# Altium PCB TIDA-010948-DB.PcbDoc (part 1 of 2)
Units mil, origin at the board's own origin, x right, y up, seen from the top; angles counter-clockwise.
Board outline 8000 x 3300 mil, 4 copper layers (Top Layer, Mid-Layer 1, Mid-Layer 2, Bottom Layer), stack 61.2 mil thick; 16 components, 34 nets, 141 pads, 139 vias.
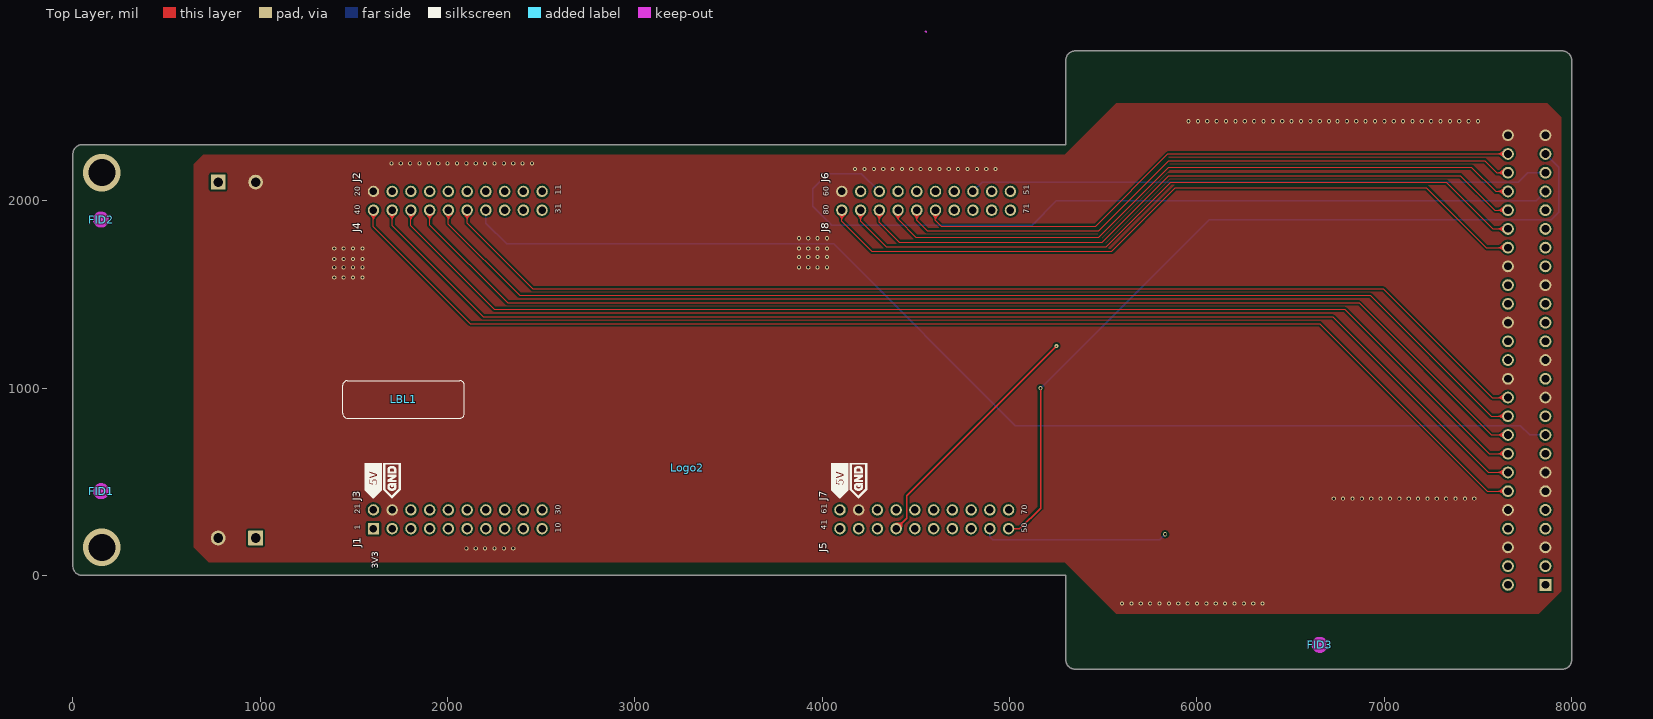
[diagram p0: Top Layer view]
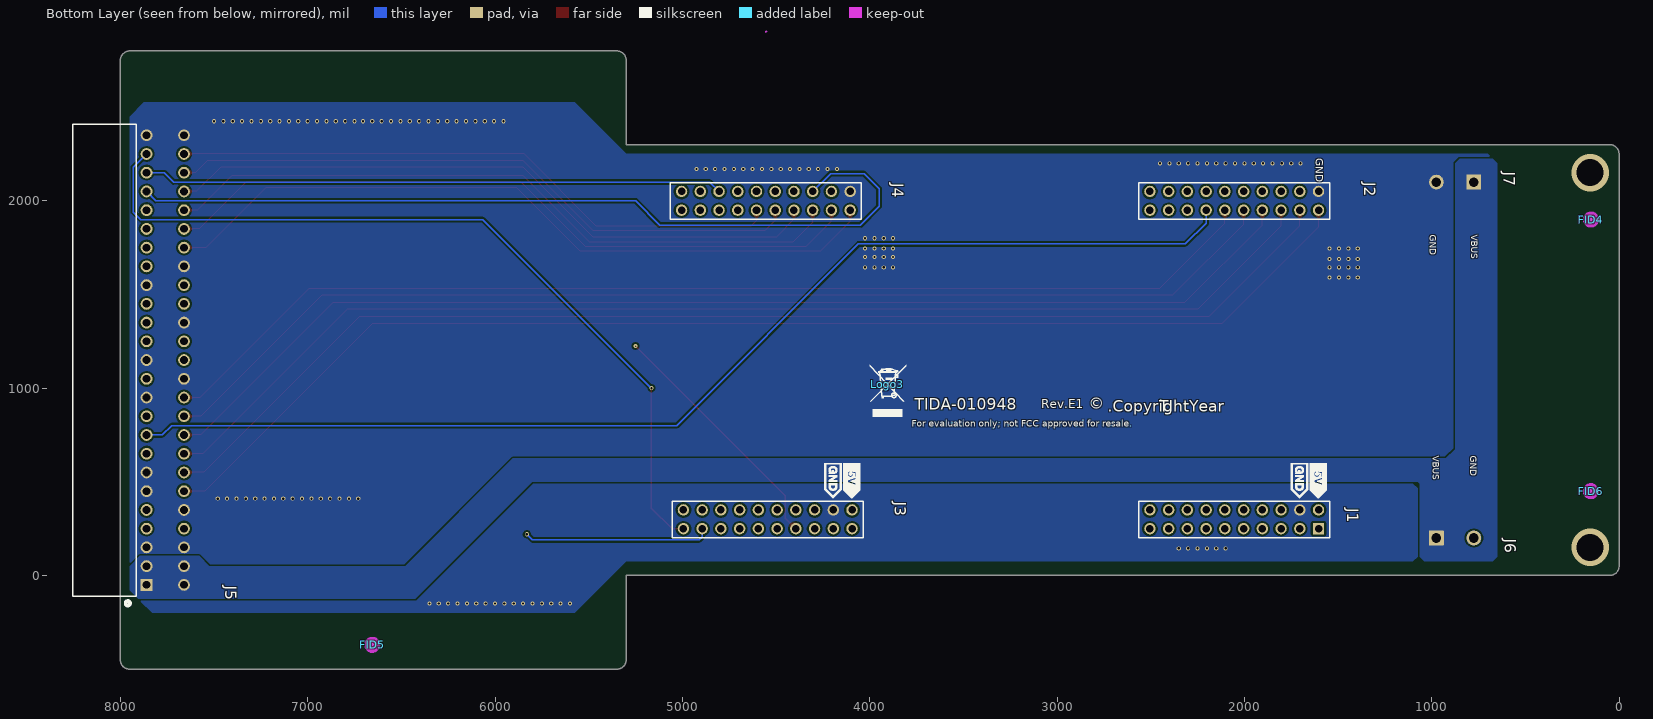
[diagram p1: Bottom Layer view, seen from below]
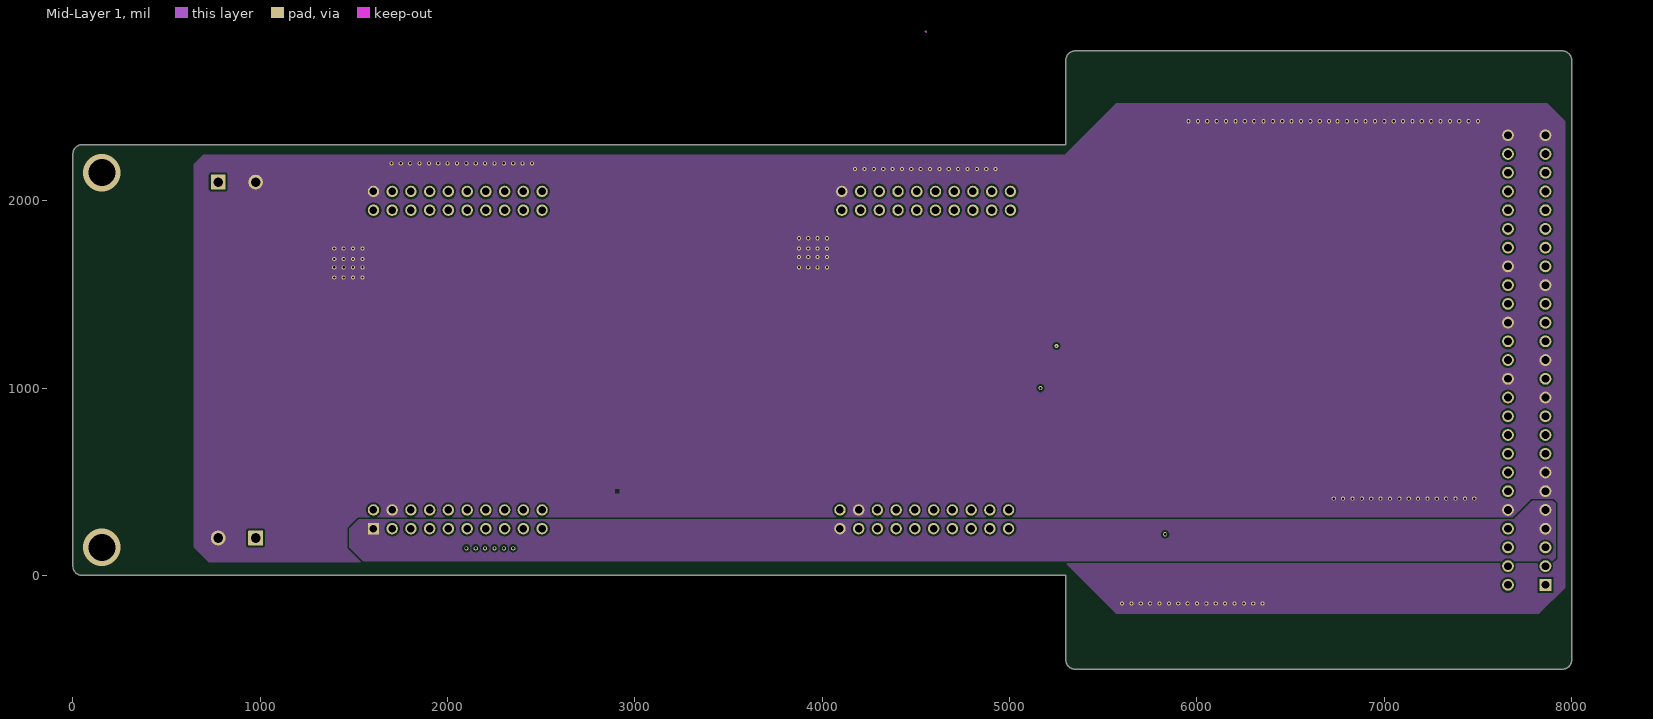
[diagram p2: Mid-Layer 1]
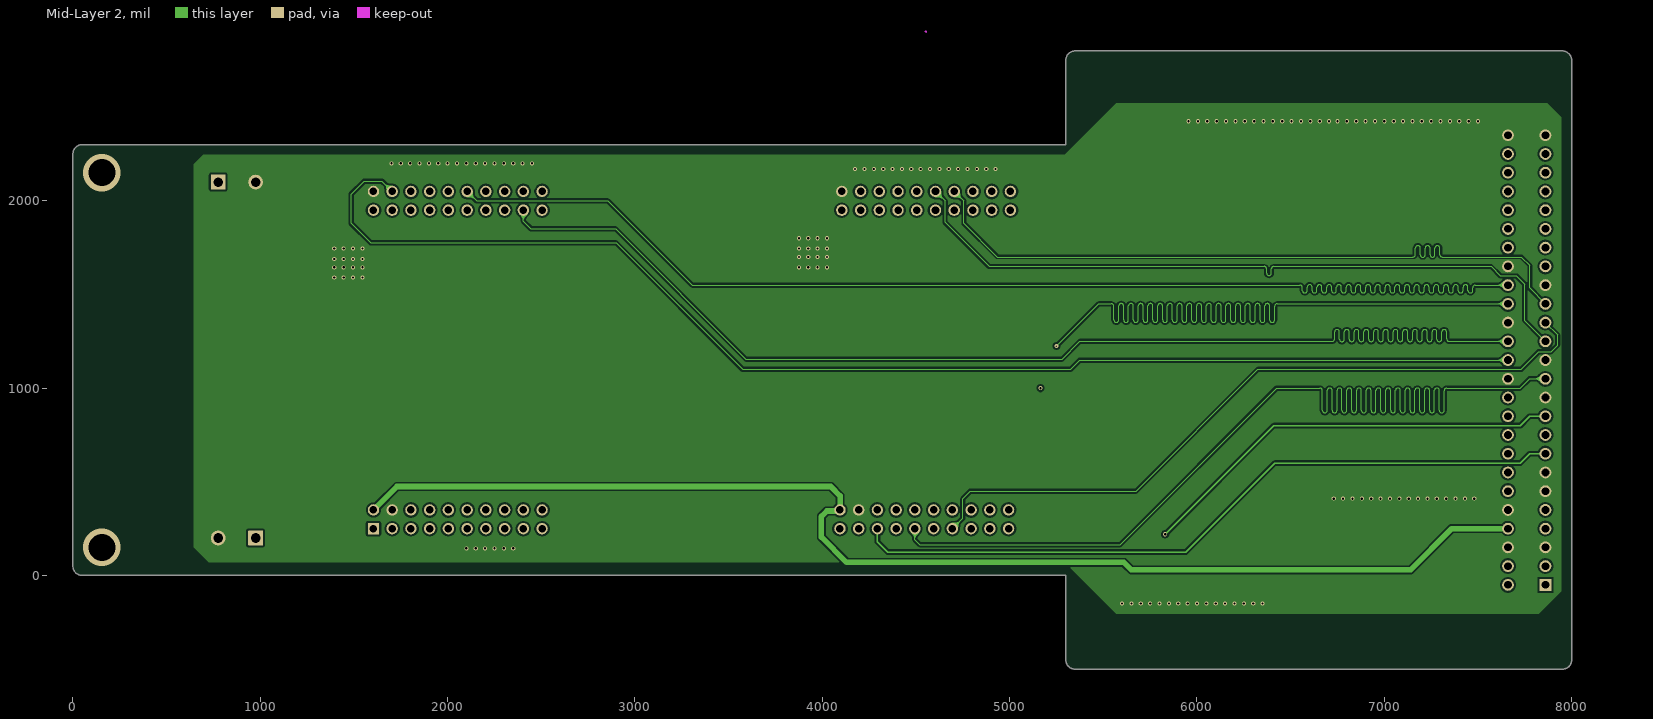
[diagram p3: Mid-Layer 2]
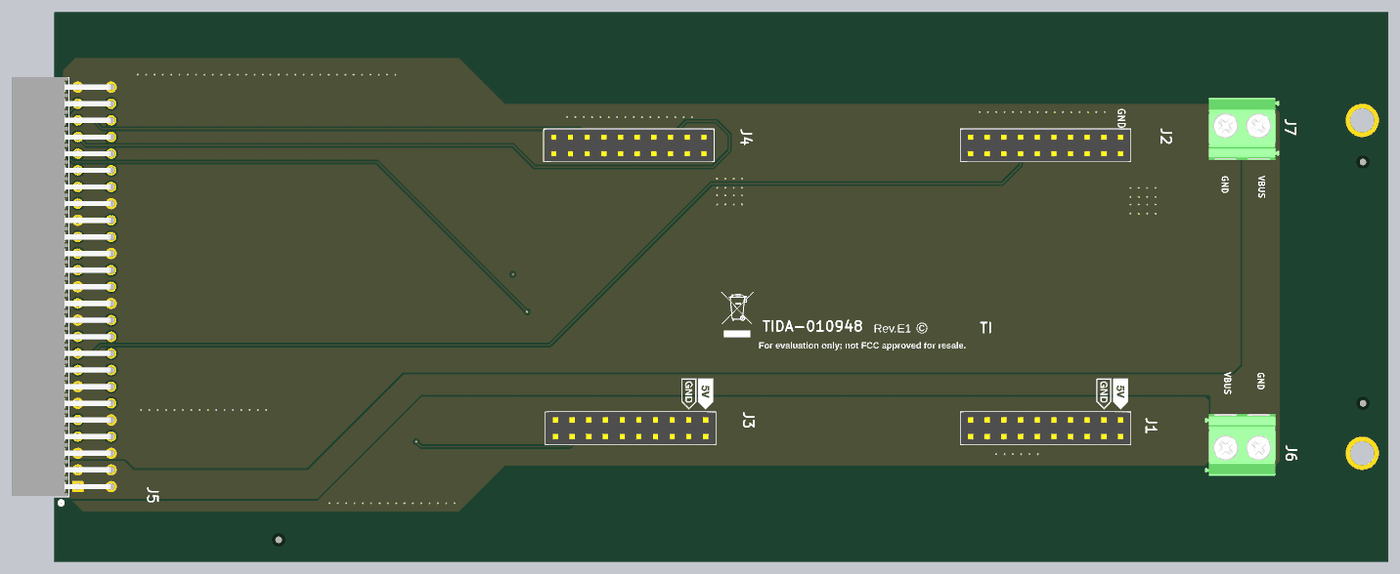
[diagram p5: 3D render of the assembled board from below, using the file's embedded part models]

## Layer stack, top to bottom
Top Solder: solder mask 0.4, Solder Resist, Dk 3.5
Top Layer: signal copper 1.4
Dielectric1: core 10, FR-4, Dk 4.2
Mid-Layer 1: signal copper 1.417
Dielectric2: prepreg 35.566, FR-4, Dk 4.2
Mid-Layer 2: signal copper 1.417
Dielectric 3: core 10, FR-4, Dk 4.2
Bottom Layer: signal copper 1.4
Bottom Solder: solder mask 0.4, Solder Resist, Dk 3.5

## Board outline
50,0 cw(c50,50) 0,50 0,2250 cw(c50,2250) 50,2300 5300,2300 5300,2749.91 cw(c5350.09,2749.91) 5350.09,2800 7950,2800 cw(c7949.39,2749.39) 8000,2748.79 8000,-450 cw(c7950,-450) 7950,-500 5350,-500 cw(c5350,-450) 5300,-450 5300,0

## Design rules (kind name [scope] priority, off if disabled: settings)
AcuteAngle [All] p1: minimum=4.50000000000000E+0001 checktracksonly=FALSE
AssemblyTestPointUsage [All] p1: valid=2
Clearance Fiducial [((Component =FID1) or (Component =FID2) or (Component =FID3) or (Component =FID4) or (Component =FID5) or (Component =FID6) or ((ObjectKind = 'Component') And (Name = 'Logo1')))] p1: gap=0 ignorepadtopadclearanceinfootprint=FALSE
Clearance Clearance_Q5 [(InNet('NetD21_2') AND InComponent('Q5')) vs (InNet('VENCODER') AND InComponent('Q5'))] p2: gap=5.51 ignorepadtopadclearanceinfootprint=FALSE except(0: Arc-Hole Track-Hole SMDPad-Hole THPad-Hole Via-Hole Fill-Hole Poly-Hole Region-Hole Text-Hole)
Clearance Clearance_Femtofet_trace [(InNet('GND') AND InComponent('Q6')) vs (InNet('NetQ6_1') AND InComponent('Q6'))] p3: gap=3.9 ignorepadtopadclearanceinfootprint=FALSE except(0: Arc-Hole Track-Hole SMDPad-Hole THPad-Hole Via-Hole Fill-Hole Poly-Hole Region-Hole Text-Hole)
Clearance Clearance_FemtoFET [IsPad AND (InComponent('Q1') or InComponent('Q2') or InComponent('Q3') or InComponent('Q4') or InComponent('Q6') or InComponent('Q7') or InComponent('Q8')) vs IsPad AND (InComponent('Q1') or InComponent('Q2') or InComponent('Q3') or InComponent('Q4') or InComponent('Q6') or InComponent('Q7') or InComponent('Q8'))] p4: gap=3.9 ignorepadtopadclearanceinfootprint=FALSE except(0: Arc-Hole Track-Hole THPad-Hole Via-Hole Fill-Hole Poly-Hole Region-Hole Text-Hole)
Clearance Clearance_Keepouts [((IsTrack Or IsArc) And Not InPoly) And IsFree and IsKeepOut vs ((IsTrack Or IsArc) And Not InPoly) And IsFree and IsKeepOut] p5: gap=0 ignorepadtopadclearanceinfootprint=FALSE
Clearance Clearance_BoardEdge_MountingHoles [OnCopper and InComponentClass('Mounting Holes') vs IsKeepOut] p6: gap=40 ignorepadtopadclearanceinfootprint=FALSE except(0: Arc-Hole Track-Hole SMDPad-Hole THPad-Hole Via-Hole Fill-Hole Poly-Hole Region-Hole Text-Hole)
Clearance Clearance_BoardEdge_Poly [OnCopper and InPoly vs IsKeepOut] p7: gap=25 ignorepadtopadclearanceinfootprint=FALSE except(0: Arc-Hole Track-Hole SMDPad-Hole THPad-Hole Via-Hole Fill-Hole Poly-Hole Region-Hole Text-Hole)
Clearance Clearance_BoardEdge [OnCopper and Not InComponentClass('Logo') and not InComponentClass('FiducialMark') and not InRegion(1000,500,4000,800) and Not IsKeepout vs IsKeepOut] p8: gap=75 ignorepadtopadclearanceinfootprint=FALSE except(0: Arc-Hole Track-Hole SMDPad-Hole THPad-Hole Via-Hole Fill-Hole Poly-Hole Region-Hole Text-Hole)
Clearance Clearance_Poly [InPolygon] p9: gap=10 ignorepadtopadclearanceinfootprint=FALSE except(0: Arc-Hole Track-Hole SMDPad-Hole THPad-Hole Via-Hole Fill-Hole Poly-Hole Region-Hole Text-Hole)
Clearance [All] p10: gap=7.87 ignorepadtopadclearanceinfootprint=FALSE except(0: Arc-Hole Track-Hole SMDPad-Hole THPad-Hole Via-Hole Fill-Hole Poly-Hole Region-Hole Text-Hole)
ComponentClearance ComponentClearance_HEADER [(ObjectKind = 'Component') And ((Name = 'J8') Or (Name='J11') or (Name='J1')or(Name='J2')) vs (ObjectKind = 'Component') And ((Name = 'J8') Or (Name='J11') or (Name='J1')or(Name='J2'))] p1: gap=0 collisioncheckmode=3 verticalgap=0 showdistances=FALSE
ComponentClearance ComponentClearance_MountingHoles_FiducialMarks [InComponentClass('Mounting Holes') vs InComponentClass('FiducialMark')] p2: gap=50 collisioncheckmode=3 verticalgap=10 showdistances=FALSE
ComponentClearance ComponentClearance_Shunt [InComponentClass('Header') vs InComponentClass('Shunt')] p3: gap=0 collisioncheckmode=3 verticalgap=0 showdistances=FALSE
ComponentClearance ComponentClearance_Logo [InComponentClass('Logo')] p4: gap=20 collisioncheckmode=3 verticalgap=10 showdistances=FALSE
ComponentClearance ComponentClearance_ScrewToNut [(HasFootprint('NY PMS 440 0025 PH')) vs (HasFootprint('Keystone_1902C'))] p5: gap=0 collisioncheckmode=3 verticalgap=0 showdistances=FALSE
ComponentClearance ComponentClearance_MountingHoles [InComponentClass('Mounting Holes')] p6: gap=50 collisioncheckmode=3 verticalgap=100000 showdistances=FALSE
ComponentClearance ComponentClearance_SmallPassives [HasFootprint('0201*') or HasFootprint('0402*') or HasFootprint('0508') or HasFootprint('0603*') or HasFootprint('0612') or HasFootprint('0805*') or HasFootprint('0815*') or HasFootprint('0830*') or HasFootprint('1206*') or HasFootprint('1210*') or HasFootprint('1808*') or HasFootprint('1812*') or HasFootprint('1825*') or HasFootprint('2010*') or HasFootprint('2220*') or HasFootprint('2225*') or HasFootprint('2512*') or HasFootprint('2728*') or HasFootprint('3518*') vs HasFootprint('0201*') or HasFootprint('0402*') or HasFootprint('0508') or HasFootprint('0603*') or HasFootprint('0612') or HasFootprint('0805*') or HasFootprint('0815*') or HasFootprint('0830*') or HasFootprint('1206*') or HasFootprint('1210*') or HasFootprint('1808*') or HasFootprint('1812*') or HasFootprint('1825*') or HasFootprint('2010*') or HasFootprint('2220*') or HasFootprint('2225*') or HasFootprint('2512*') or HasFootprint('2728*') or HasFootprint('3518*')] p7: gap=20 collisioncheckmode=3 verticalgap=10 showdistances=FALSE
ComponentClearance ComponentClearance_THtoSMT [IsThruComponent vs IsSMTComponent] p8: gap=80 collisioncheckmode=3 verticalgap=30 showdistances=FALSE
ComponentClearance ComponentClearance_THtoTH [IsThruComponent vs IsThruComponent] p9: gap=80 collisioncheckmode=3 verticalgap=30 showdistances=FALSE
ComponentClearance [All] p10: gap=40 collisioncheckmode=3 verticalgap=10 showdistances=FALSE
DiffPairsRouting [All] p1: maxlimit=100 minlimit=10 mostfreqgap=10 toplayer_minwidth=15 toplayer_maxwidth=15 toplayer_prefwidth=15 midlayer1_minwidth=15 midlayer1_maxwidth=15 midlayer1_prefwidth=15 midlayer2_minwidth=15 midlayer2_maxwidth=15 midlayer2_prefwidth=15 bottomlayer_minwidth=15 bottomlayer_maxwidth=15 bottomlayer_prefwidth=15 substack1={F209BFA6-9EB9-4928-9A79-C4DA4B168F69} toplayer_{f209bfa6-9eb9-4928-9a79-c4da4b168f69}_minwidth=15 toplayer_{f209bfa6-9eb9-4928-9a79-c4da4b168f69}_maxwidth=15 toplayer_{f209bfa6-9eb9-4928-9a79-c4da4b168f69}_prefwidth=15 midlayer1_{f209bfa6-9eb9-4928-9a79-c4da4b168f69}_minwidth=15 midlayer1_{f209bfa6-9eb9-4928-9a79-c4da4b168f69}_maxwidth=15 midlayer1_{f209bfa6-9eb9-4928-9a79-c4da4b168f69}_prefwidth=15 midlayer2_{f209bfa6-9eb9-4928-9a79-c4da4b168f69}_minwidth=15 midlayer2_{f209bfa6-9eb9-4928-9a79-c4da4b168f69}_maxwidth=15 midlayer2_{f209bfa6-9eb9-4928-9a79-c4da4b168f69}_prefwidth=15 bottomlayer_{f209bfa6-9eb9-4928-9a79-c4da4b168f69}_minwidth=15 bottomlayer_{f209bfa6-9eb9-4928-9a79-c4da4b168f69}_maxwidth=15 bottomlayer_{f209bfa6-9eb9-4928-9a79-c4da4b168f69}_prefwidth=15 maxuncoupledlength=1000
FabricationTestPointUsage TestPointUsage [All] p1: valid=2 allowmultiple=FALSE
FabricationTestpoint Testpoint [All] p1: side=3 testpointundercomponent=TRUE minsize=40 maxsize=100 preferedsize=60 minholesize=0 maxholesize=40 preferedholesize=32 testpointgrid=1 allowsidetop=TRUE allowsidebottom=TRUE usegrid=TRUE gridtolerance=0.01
FanoutControl Fanout_LCC [IsLCC] p1: bgadir=Out bgaviamode=Centered fanoutstyle=Auto fanoutdirection=Alternating viagrid=1 // Fanout_LCC (Default Rule)
FanoutControl Fanout_BGA [IsBGA] p2: bgadir=Out bgaviamode=Centered fanoutstyle=Auto fanoutdirection=Alternating viagrid=1 // Fanout_BGA (Default Rule)
FanoutControl Fanout_Default [All] p4: bgadir=Out bgaviamode=Centered fanoutstyle=Auto fanoutdirection=Alternating viagrid=1 // Fanout_Default (Default Rule)
FanoutControl Fanout_Small [(CompPinCount < 5)] p5: bgadir=Out bgaviamode=Centered fanoutstyle=Auto fanoutdirection=OutThenIn viagrid=1 // Fanout_Small (Default Rule)
HoleSize [All] p1: absolutevalues=TRUE maxlimit=251 minlimit=7 maxpercent=80.000 minpercent=20.000
MinimumAnnularRing MinimumAnnularRing_ThermalPadVias [IsVia and InAnyComponent] p1: minimumring=5
MinimumAnnularRing [All] p2: minimumring=5
MinimumSolderMaskSliver MinimumSolderMaskSliver_Logo [InComponentClass('Logo') vs InComponentClass('Logo')] p1: minsoldermaskwidth=0.7
MinimumSolderMaskSliver [All] p2: minsoldermaskwidth=2
NetAntennae [not(InComponent ('U4') and IsVia)] p1: netantennaetolerance=0
PlaneConnect [All] p1: planeconnectstyle=Relief reliefexpansion=10 reliefentries=4 reliefconductorwidth=10 reliefairgap=10
PolygonConnect PolygonConnect_47 [All vs IsNamedPolygon('Top Layer -GND')] p1: connectstyle=Direct reliefconductorwidth=10 reliefentries=4 polygonreliefangle="90 Angle" airgapwidth=10
PolygonConnect PolygonConnect_46 [All vs IsNamedPolygon('Top Layer-No Net 9')] p2: connectstyle=Direct reliefconductorwidth=10 reliefentries=4 polygonreliefangle="90 Angle" airgapwidth=10
PolygonConnect PolygonConnect_45 [All vs IsNamedPolygon('Top Layer-No Net 9')] p3: connectstyle=Direct reliefconductorwidth=10 reliefentries=4 polygonreliefangle="90 Angle" airgapwidth=10
PolygonConnect PolygonConnect_44 [All vs IsNamedPolygon('Top Layer-No Net 9')] p4: connectstyle=Direct reliefconductorwidth=10 reliefentries=4 polygonreliefangle="90 Angle" airgapwidth=10
PolygonConnect PolygonConnect_43 [All vs IsNamedPolygon('Top Layer-No Net 9')] p5: connectstyle=Direct reliefconductorwidth=10 reliefentries=4 polygonreliefangle="90 Angle" airgapwidth=10
PolygonConnect PolygonConnect_42 [All vs IsNamedPolygon('Top Layer-No Net 9')] p6: connectstyle=Direct reliefconductorwidth=10 reliefentries=4 polygonreliefangle="90 Angle" airgapwidth=10
PolygonConnect PolygonConnect_41 [All vs IsNamedPolygon('Top Layer-No Net 9')] p7: connectstyle=Direct reliefconductorwidth=10 reliefentries=4 polygonreliefangle="90 Angle" airgapwidth=10
PolygonConnect PolygonConnect_40 [All vs IsNamedPolygon('Top Layer-No Net 8')] p8: connectstyle=Direct reliefconductorwidth=10 reliefentries=4 polygonreliefangle="90 Angle" airgapwidth=10
PolygonConnect PolygonConnect_39 [All vs IsNamedPolygon('Top Layer-No Net 8')] p9: connectstyle=Direct reliefconductorwidth=10 reliefentries=4 polygonreliefangle="90 Angle" airgapwidth=10
PolygonConnect PolygonConnect_38 [All vs IsNamedPolygon('Top Layer-No Net 7')] p10: connectstyle=Direct reliefconductorwidth=10 reliefentries=4 polygonreliefangle="90 Angle" airgapwidth=10
PolygonConnect PolygonConnect_37 [All vs IsNamedPolygon('Top Layer-No Net 7')] p11: connectstyle=Direct reliefconductorwidth=10 reliefentries=4 polygonreliefangle="90 Angle" airgapwidth=10
PolygonConnect PolygonConnect_36 [All vs IsNamedPolygon('Bottom Layer-No Net 3')] p12: connectstyle=Direct reliefconductorwidth=10 reliefentries=4 polygonreliefangle="90 Angle" airgapwidth=10
PolygonConnect PolygonConnect_35 [All vs IsNamedPolygon('Bottom Layer-No Net 3')] p13: connectstyle=Direct reliefconductorwidth=10 reliefentries=4 polygonreliefangle="90 Angle" airgapwidth=10
PolygonConnect PolygonConnect_34 [All vs IsNamedPolygon('Bottom Layer-No Net 3')] p14: connectstyle=Direct reliefconductorwidth=10 reliefentries=4 polygonreliefangle="90 Angle" airgapwidth=10
PolygonConnect PolygonConnect_33 [All vs IsNamedPolygon('Bottom Layer-No Net 2')] p15: connectstyle=Direct reliefconductorwidth=10 reliefentries=4 polygonreliefangle="90 Angle" airgapwidth=10
PolygonConnect PolygonConnect_32 [All vs IsNamedPolygon('Bottom Layer-No Net')] p16: connectstyle=Direct reliefconductorwidth=10 reliefentries=4 polygonreliefangle="90 Angle" airgapwidth=10
PolygonConnect PolygonConnect_31 [All vs IsNamedPolygon('Bottom Layer-No Net 1')] p17: connectstyle=Direct reliefconductorwidth=10 reliefentries=4 polygonreliefangle="90 Angle" airgapwidth=10
PolygonConnect PolygonConnect_30 [All vs IsNamedPolygon('Bottom Layer-No Net')] p18: connectstyle=Direct reliefconductorwidth=10 reliefentries=4 polygonreliefangle="90 Angle" airgapwidth=10
PolygonConnect PolygonConnect_29 [All vs IsNamedPolygon('Bottom Layer-No Net 1')] p19: connectstyle=Direct reliefconductorwidth=10 reliefentries=4 polygonreliefangle="90 Angle" airgapwidth=10
PolygonConnect PolygonConnect_28 [All vs IsNamedPolygon('Top Layer -GND')] p20: connectstyle=Direct reliefconductorwidth=10 reliefentries=4 polygonreliefangle="90 Angle" airgapwidth=10
PolygonConnect PolygonConnect_27 [All vs IsNamedPolygon('Top Layer -GND')] p21: connectstyle=Direct reliefconductorwidth=10 reliefentries=4 polygonreliefangle="90 Angle" airgapwidth=10
PolygonConnect PolygonConnect_26 [All vs IsNamedPolygon('Top Layer -GND')] p22: connectstyle=Direct reliefconductorwidth=10 reliefentries=4 polygonreliefangle="90 Angle" airgapwidth=10
PolygonConnect PolygonConnect_25 [All vs IsNamedPolygon('Top Layer -VIN')] p23: connectstyle=Direct reliefconductorwidth=10 reliefentries=4 polygonreliefangle="90 Angle" airgapwidth=10
PolygonConnect PolygonConnect_24 [All vs IsNamedPolygon('Top Layer -VIN')] p24: connectstyle=Direct reliefconductorwidth=10 reliefentries=4 polygonreliefangle="90 Angle" airgapwidth=10
PolygonConnect PolygonConnect_23 [All vs IsNamedPolygon('Top Layer -VIN')] p25: connectstyle=Direct reliefconductorwidth=10 reliefentries=4 polygonreliefangle="90 Angle" airgapwidth=10
PolygonConnect PolygonConnect_22 [All vs IsNamedPolygon('Top Layer-No Net 4')] p26: connectstyle=Direct reliefconductorwidth=10 reliefentries=4 polygonreliefangle="90 Angle" airgapwidth=10
PolygonConnect PolygonConnect_21 [All vs IsNamedPolygon('Top Layer-No Net 6')] p27: connectstyle=Direct reliefconductorwidth=10 reliefentries=4 polygonreliefangle="90 Angle" airgapwidth=10
PolygonConnect PolygonConnect_20 [All vs IsNamedPolygon('Top Layer-No Net')] p28: connectstyle=Direct reliefconductorwidth=10 reliefentries=4 polygonreliefangle="90 Angle" airgapwidth=10
PolygonConnect PolygonConnect_19 [All vs IsNamedPolygon('Top Layer-No Net 1')] p29: connectstyle=Direct reliefconductorwidth=10 reliefentries=4 polygonreliefangle="90 Angle" airgapwidth=10
PolygonConnect PolygonConnect_18 [All vs IsNamedPolygon('Top Layer -PHASE')] p30: connectstyle=Direct reliefconductorwidth=10 reliefentries=4 polygonreliefangle="90 Angle" airgapwidth=10
PolygonConnect PolygonConnect_17 [All vs IsNamedPolygon('Bottom Layer -GND')] p31: connectstyle=Direct reliefconductorwidth=10 reliefentries=4 polygonreliefangle="90 Angle" airgapwidth=10
PolygonConnect PolygonConnect_16 [All vs IsNamedPolygon('Top Layer-No Net 3')] p32: connectstyle=Direct reliefconductorwidth=10 reliefentries=4 polygonreliefangle="90 Angle" airgapwidth=10
PolygonConnect PolygonConnect_15 [All vs IsNamedPolygon('Mid-Layer 2 -GND')] p33: connectstyle=Direct reliefconductorwidth=10 reliefentries=4 polygonreliefangle="90 Angle" airgapwidth=10
PolygonConnect PolygonConnect_14 [All vs IsNamedPolygon('Top Layer -VENCODER')] p34: connectstyle=Direct reliefconductorwidth=10 reliefentries=4 polygonreliefangle="90 Angle" airgapwidth=10
PolygonConnect PolygonConnect_13 [All vs IsNamedPolygon('Top Layer-No Net 2')] p35: connectstyle=Direct reliefconductorwidth=10 reliefentries=4 polygonreliefangle="90 Angle" airgapwidth=10
PolygonConnect PolygonConnect_12 [All vs IsNamedPolygon('Top Layer-No Net 5')] p36: connectstyle=Direct reliefconductorwidth=10 reliefentries=4 polygonreliefangle="90 Angle" airgapwidth=10
PolygonConnect PolygonConnect_11 [All vs IsNamedPolygon('Top Layer -VOUT_EFUSE')] p37: connectstyle=Direct reliefconductorwidth=10 reliefentries=4 polygonreliefangle="90 Angle" airgapwidth=10
PolygonConnect PolygonConnect_10 [All vs IsNamedPolygon('Top Layer-No Net 3')] p38: connectstyle=Direct reliefconductorwidth=10 reliefentries=4 polygonreliefangle="90 Angle" airgapwidth=10
PolygonConnect PolygonConnect_9 [All vs IsNamedPolygon('Top Layer-No Net')] p39: connectstyle=Direct reliefconductorwidth=10 reliefentries=4 polygonreliefangle="90 Angle" airgapwidth=10
PolygonConnect PolygonConnect_8 [All vs IsNamedPolygon('Mid-Layer 2 -GND')] p40: connectstyle=Direct reliefconductorwidth=10 reliefentries=4 polygonreliefangle="90 Angle" airgapwidth=10
PolygonConnect PolygonConnect_7 [All vs IsNamedPolygon('Top Layer -VENCODER')] p41: connectstyle=Direct reliefconductorwidth=10 reliefentries=4 polygonreliefangle="90 Angle" airgapwidth=10
PolygonConnect PolygonConnect_6 [All vs IsNamedPolygon('Top Layer -PHASE')] p42: connectstyle=Direct reliefconductorwidth=10 reliefentries=4 polygonreliefangle="90 Angle" airgapwidth=10
PolygonConnect PolygonConnect_5 [All vs IsNamedPolygon('Top Layer -VOUT_EFUSE')] p43: connectstyle=Direct reliefconductorwidth=10 reliefentries=4 polygonreliefangle="90 Angle" airgapwidth=10
PolygonConnect PolygonConnect_4 [All vs IsNamedPolygon('Bottom Layer -GND')] p44: connectstyle=Direct reliefconductorwidth=10 reliefentries=4 polygonreliefangle="90 Angle" airgapwidth=10
PolygonConnect PolygonConnect_3 [All vs IsNamedPolygon('Mid-Layer 2-No Net')] p45: connectstyle=Direct reliefconductorwidth=10 reliefentries=4 polygonreliefangle="90 Angle" airgapwidth=10
PolygonConnect PolygonConnect_2 [All vs IsNamedPolygon('GND')] p46: connectstyle=Direct reliefconductorwidth=10 reliefentries=4 polygonreliefangle="90 Angle" airgapwidth=10
PolygonConnect PolygonConnect_1 [All vs IsNamedPolygon('Bottom Layer-No Net')] p47: connectstyle=Direct reliefconductorwidth=10 reliefentries=4 polygonreliefangle="90 Angle" airgapwidth=10
PolygonConnect [All] p48: connectstyle=Direct reliefconductorwidth=20 reliefentries=4 polygonreliefangle="90 Angle" airgapwidth=10
RoutingVias ThermalPadVias [IsVia and InAnyComponent] p1: holewidth=7.87 width=19.68 viastyle="Through Hole" minholewidth=7 minwidth=19.68 maxholewidth=13 maxwidth=23.62
RoutingVias [All] p2: holewidth=16 width=34 viastyle="Through Hole" minholewidth=7.87 minwidth=19 maxholewidth=40 maxwidth=65
SilkToBoardRegionClearance [Not ((IsComment or IsDesignator) And (Hide <> 'False')) and not (InRegion(1000,500,4000,800) or InRegion(1600,4700,2200,4785) or InRegion(4700,2500,4850,4250))] p1:
SilkToSilkClearance SilkToSilkClearance_Pb-FreeLogo [(HasFootprint('Pb-Free_Overlay_Medium') OR HasFootprint('Pb-Free_Overlay_Small')) vs (HasFootprint('Pb-Free_Overlay_Medium') OR HasFootprint('Pb-Free_Overlay_Small'))] p1: silktosilkclearance=0
SilkToSilkClearance [All] p2: silktosilkclearance=0
SilkToSolderMaskClearance "Silk to Solder Mask Opening" [not (IsVia) vs not (IsVia)] p1: minsilkscreentomaskgap=0 clearancetoexposedcopper=FALSE
SolderMaskExpansion [All] p1: expansion=1.97 istentingtop=FALSE
SupplyNets "Schematic Supply Nets_3" [InNet('GND')] p1: voltage=0.000
SupplyNets "Schematic Supply Nets_2" [InNet('VSYS_5V0')] p2: voltage=0.000
SupplyNets "Schematic Supply Nets_1" [InNet('VBUS')] p3: voltage=0.000
SupplyNets "Schematic Supply Nets" [InNet('VSYS_3V3')] p4: voltage=0.000
Width [All] p1: maxlimit=100 minlimit=6 preferedwidth=10 substack1={F209BFA6-9EB9-4928-9A79-C4DA4B168F69} checkconnectedcopper=TRUE
14 further rules are at their usual default settings.

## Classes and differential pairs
net class DRV_SPI: DRV_SPI_CLK DRV_SPI_D0 DRV_SPI_D1
net class SDM: DOUT1_A1 DOUT1_A2 DOUT1_B1 DOUT1_B2 SDFM_CLK_SOURCE_BUF
component class Label: LBL1
component class TIDA-010948-DB-Interface: J1 J2 J3 J4 J5 J6 J7
component class TIDA-010948-DB-Hardware: FID1 FID2 FID3 FID4 FID5 FID6 LBL1 Logo2 Logo3
component class FiducialMark: FID1 FID2 FID3 FID4 FID5 FID6

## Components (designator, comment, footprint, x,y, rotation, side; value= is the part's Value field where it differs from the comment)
FID1 "Fiducial" Fiducial10-20 150,450 r0 top
FID2 "Fiducial" Fiducial10-20 150,1900 r0 top
FID3 "Fiducial" Fiducial10-20 6655,-370 r0 top
FID4 "Fiducial" Fiducial10-20 150,1900 r90 bottom
FID5 "Fiducial" Fiducial10-20 6655,-370 r90 bottom
FID6 "Fiducial" Fiducial10-20 150,450 r90 bottom
J1 "SSQ-110-03-T-D" BoosterPack_40pin_J1J3 2054.18,300 r270 bottom locked
J2 "SSQ-110-03-T-D" BoosterPack_40pin_J2J4 2054.18,2000 r270 bottom locked
J3 "SSQ-110-03-T-D" BoosterPack_40pin_J5J7 4544.19,300 r270 bottom locked
J4 "SSQ-110-03-T-D" BoosterPack_40pin_J6J8 4554.18,2000 r270 bottom locked
J5 "SSW-125-02-T-Q-RA" Samtec_SSW-125-02-T-Q-RA 7760,1150 r270 bottom locked
J6 "1711725" FP-1888687_HDR2-MFG 875,200 r180 bottom
J7 "1711725" FP-1888687_HDR2-MFG 875,2100 r0 bottom locked
LBL1 "THT-14-423-10" Label_650x200 1765,940 r0 top
Logo2 "FCC disclaimer" FCC_disclaimer 3278,576 r90 top
Logo3 "WEEE logo" WEEE_Minimum 3905,1020 r180 bottom

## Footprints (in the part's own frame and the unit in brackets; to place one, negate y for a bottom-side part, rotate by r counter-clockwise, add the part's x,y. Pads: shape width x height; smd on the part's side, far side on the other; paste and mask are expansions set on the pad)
BoosterPack_40pin_J1J3 [mm] "Receptacle, 2.54mm, 10x2, TH"
  rrect6% 1.55x1.55 hole 1.02: 1(1.27,11.43)
  round 1.55 hole 1.02: 2(1.27,8.89) 3(1.27,6.35) 4(1.27,3.81) 5(1.27,1.27) 6(1.27,-1.27) 7(1.27,-3.81) 8(1.27,-6.35) 9(1.27,-8.89) 10(1.27,-11.43) 21(-1.27,11.43) 22(-1.27,8.89) 23(-1.27,6.35) 24(-1.27,3.81) 25(-1.27,1.27) 26(-1.27,-1.27) 27(-1.27,-3.81) 28(-1.27,-6.35) 29(-1.27,-8.89) 30(-1.27,-11.43)
  silkscreen extent -7.62,-12.95 2.48,12.95, body extent -2.48,-12.95 2.48,12.95, height 8.51
BoosterPack_40pin_J2J4 [mm] "Receptacle, 2.54mm, 10x2, TH"
  round 1.55 hole 1.02: 11(-1.27,-11.43) 12(-1.27,-8.89) 13(-1.27,-6.35) 14(-1.27,-3.81) 15(-1.27,-1.27) 16(-1.27,1.27) 17(-1.27,3.81) 18(-1.27,6.35) 19(-1.27,8.89) 20(-1.27,11.43) 31(1.27,-11.43) 32(1.27,-8.89) 33(1.27,-6.35) 34(1.27,-3.81) 35(1.27,-1.27) 36(1.27,1.27) 37(1.27,3.81) 38(1.27,6.35) 39(1.27,8.89) 40(1.27,11.43)
  silkscreen extent -2.48,-12.95 2.48,12.95, body extent -2.48,-12.95 2.48,12.95, height 8.51
BoosterPack_40pin_J5J7 [mm] "Receptacle, 2.54mm, 10x2, TH"
  round 1.55 hole 1.02: 41(1.27,11.43) 42(1.27,8.89) 43(1.27,6.35) 44(1.27,3.81) 45(1.27,1.27) 46(1.27,-1.27) 47(1.27,-3.81) 48(1.27,-6.35) 49(1.27,-8.89) 50(1.27,-11.43) 61(-1.27,11.43) 62(-1.27,8.89) 63(-1.27,6.35) 64(-1.27,3.81) 65(-1.27,1.27) 66(-1.27,-1.27) 67(-1.27,-3.81) 68(-1.27,-6.35) 69(-1.27,-8.89) 70(-1.27,-11.43)
  silkscreen extent -7.62,-12.95 2.48,12.95, body extent -2.48,-12.95 2.48,12.95, height 8.51
BoosterPack_40pin_J6J8 [mm] "Receptacle, 2.54mm, 10x2, TH"
  round 1.55 hole 1.02: 51(-1.27,-11.43) 52(-1.27,-8.89) 53(-1.27,-6.35) 54(-1.27,-3.81) 55(-1.27,-1.27) 56(-1.27,1.27) 57(-1.27,3.81) 58(-1.27,6.35) 59(-1.27,8.89) 60(-1.27,11.43) 71(1.27,-11.43) 72(1.27,-8.89) 73(1.27,-6.35) 74(1.27,-3.81) 75(1.27,-1.27) 76(1.27,1.27) 77(1.27,3.81) 78(1.27,6.35) 79(1.27,8.89) 80(1.27,11.43)
  silkscreen extent -2.48,-12.95 2.48,12.95, body extent -2.48,-12.95 2.48,12.95, height 8.51
FCC_disclaimer [mil]
Fiducial10-20 [mm]
  round 1 smd mask+0.5: 1(0,0)
  Top Layer keep-out circle w1.178: c0,0 r0.5
FP-1888687_HDR2-MFG [mm]
  rrect5% 2x2 hole 1.3 paste-2539.97 mask+0: 1(-2.54,0)
  round 2 hole 1.3 paste-2539.97 mask+0: 2(2.54,0)
  body extent -5.65,-4.75 5.08,4.75, height 15.15
Label_650x200 [mil] "Thermal Transfer Label"
  round 1 on Mech13: 0(0,0)
  silkscreen extent -325,-100 325,100, body extent -325,-100 325,100, height 1
Samtec_SSW-125-02-T-Q-RA [mm] "SAMTEC"
  rect 1.6x1.6 hole 1.04: 1(30.48,-2.54)
  round 1.6 hole 1.04: 3(30.48,2.54) 4(27.94,-2.54) 6(27.94,2.54) 7(25.4,-2.54) 9(25.4,2.54) 10(22.86,-2.54) 12(22.86,2.54) 13(20.32,-2.54) 15(20.32,2.54) 16(17.78,-2.54) 18(17.78,2.54) 19(15.24,-2.54) 21(15.24,2.54) 22(12.7,-2.54) 24(12.7,2.54) 25(10.16,-2.54) 27(10.16,2.54) 28(7.62,-2.54) 30(7.62,2.54) 31(5.08,-2.54) 33(5.08,2.54) 34(2.54,-2.54) 36(2.54,2.54) 37(0,-2.54) 39(0,2.54) 40(-2.54,-2.54) 42(-2.54,2.54) 43(-5.08,-2.54) 45(-5.08,2.54) 46(-7.62,-2.54) 48(-7.62,2.54) 49(-10.16,-2.54) 51(-10.16,2.54) 52(-12.7,-2.54) 54(-12.7,2.54) 55(-15.24,-2.54) 57(-15.24,2.54) 58(-17.78,-2.54) 60(-17.78,2.54) 61(-20.32,-2.54) 63(-20.32,2.54) 64(-22.86,-2.54) 66(-22.86,2.54) 67(-25.4,-2.54) 69(-25.4,2.54) 70(-27.94,-2.54) 72(-27.94,2.54) 73(-30.48,-2.54) 75(-30.48,2.54)
  silkscreen extent -31.95,-12.52 33.27,-3.92, body extent -32,-12.57 32,2.74, height 7.51
WEEE_Minimum [mil] "WEEElie bin"
  silkscreen extent -95,-172 99,104

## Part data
FID1 FID2 FID3 FID4 FID5 FID6: library part CMP-0077181-1, "Fiducial mark.  There is nothing to buy or mount.", Manufacturer=N/A
J1: library part CMP-0003837-4, "Receptacle, 2.54mm, 10x2, Tin, TH", Alternate Manufacturer="Major League Electronics", Alternate PartNumber=CRD-081413-A-G, Manufacturer=Samtec, Supplier Part Number 1=SAM1204-10-ND
J2: library part CMP-0078266-4, "Receptacle, 2.54mm, 10x2, Tin, TH", Alternate Manufacturer="Major League Electronics", Alternate PartNumber=CRD-081413-A-G, Manufacturer=Samtec, Supplier Part Number 1=SAM1204-10-ND
J3: library part CMP-0081070-3, "Receptacle, 2.54mm, 10x2, Tin, TH", Alternate Manufacturer="Major League Electronics", Alternate PartNumber=CRD-081413-A-G, Manufacturer=Samtec, Supplier Part Number 1=SAM1204-10-ND
J4: library part CMP-0081071-3, "Receptacle, 2.54mm, 10x2, Tin, TH", Alternate Manufacturer="Major League Electronics", Alternate PartNumber=CRD-081413-A-G, Manufacturer=Samtec, Supplier Part Number 1=SAM1204-10-ND
J5: library part CMP-0055988-1, "Receptacle, 100mil, 25x2, R/A, TIN, TH", Manufacturer=Samtec
J6 J7: library part CMP-0087130-1, Current_A=15A, Manufacturer="Phoenix Contact", Voltage_V=400V
LBL1: library part CMP-0003625-1, "Thermal Transfer Printable Labels, 0.650\" W x 0.200\" H - 10,000 per roll", Manufacturer=Brady, Supplier Part Number 1=97C5133
Logo2: library part CMP-0074847-1, "FCC_disclaimer"
Logo3: library part CMP-0074769-1

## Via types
v1: diameter 22, hole 12, Top Layer to Bottom Layer, tented both sides, 136 vias
v2: diameter 200, hole 144, Top Layer to Bottom Layer, 2 vias
v3: diameter 22, hole 8, Top Layer to Bottom Layer, tented both sides, 1 vias

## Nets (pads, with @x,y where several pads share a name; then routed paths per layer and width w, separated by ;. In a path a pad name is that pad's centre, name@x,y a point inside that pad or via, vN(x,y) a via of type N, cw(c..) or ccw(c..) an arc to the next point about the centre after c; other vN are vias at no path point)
DOUT1_A1: J2.32 J5.42 | length 6945.7
  Mid-Layer 2 w6: J2.32@2404.18,1950 2404.18,1890.82 2445,1850 2897,1850 3592,1155 5280,1155 5375,1250 6684.26,1250 6721.5,1250 ccw(c6721.5,1263) 6734.5,1263 6734.5,1299.9 cw(c6747.5,1299.9) 6760.5,1299.9 6760.5,1260.97 ccw(c6773.5,1260.97) 6786.5,1260.97 6786.5,1299.9 cw(c6799.5,1299.9) 6812.5,1299.9 6812.5,1260.97 ccw(c6825.5,1260.97) 6838.5,1260.97 6838.5,1299.9 cw(c6851.5,1299.9) 6864.5,1299.9 6864.5,1260.97 ccw(c6877.5,1260.97) 6890.5,1260.97 6890.5,1299.9 cw(c6903.5,1299.9) 6916.5,1299.9 6916.5,1260.97 ccw(c6929.5,1260.97) 6942.5,1260.97 6942.5,1299.9 cw(c6955.5,1299.9) 6968.5,1299.9 6968.5,1260.97 ccw(c6981.5,1260.97) 6994.5,1260.97 6994.5,1299.9 cw(c7007.5,1299.9) 7020.5,1299.9 7020.5,1260.97 ccw(c7033.5,1260.97) 7046.5,1260.97 7046.5,1299.9 cw(c7059.5,1299.9) 7072.5,1299.9 7072.5,1260.97 ccw(c7085.5,1260.97) 7098.5,1260.97 7098.5,1299.9 cw(c7111.5,1299.9) 7124.5,1299.9 7124.5,1260.97 ccw(c7137.5,1260.97) 7150.5,1260.97 7150.5,1299.9 cw(c7163.5,1299.9) 7176.5,1299.9 7176.5,1260.97 ccw(c7189.5,1260.97) 7202.5,1260.97 7202.5,1299.9 cw(c7215.5,1299.9) 7228.5,1299.9 7228.5,1260.97 ccw(c7241.5,1260.97) 7254.5,1260.97 7254.5,1299.9 cw(c7267.5,1299.9) 7280.5,1299.9 7280.5,1260.97 ccw(c7293.5,1260.97) 7306.5,1260.97 7306.5,1299.9 cw(c7319.5,1299.9) 7332.5,1299.9 7332.5,1263 ccw(c7345.5,1263) 7345.5,1250 7374.5,1250 J5.42@7660,1250
DOUT1_A2: J3.44 J5.48 | length 6895.2
  Top Layer w8: J3.44@4394.19,250 4450,305.81 4450,425 v3(5250,1225)
  Mid-Layer 2 w6: v3(5250,1225) 5475,1450 5514.38,1450 5543.38,1450 cw(c5543.38,1437) 5556.38,1437 5556.38,1363.9 ccw(c5569.38,1363.9) 5582.38,1363.9 5582.38,1439.25 cw(c5595.38,1439.25) 5608.38,1439.25 5608.38,1363.88 ccw(c5621.38,1363.88) 5634.38,1363.88 5634.38,1439.23 cw(c5647.38,1439.23) 5660.38,1439.23 5660.38,1363.87 ccw(c5673.38,1363.87) 5686.38,1363.87 5686.38,1439.22 cw(c5699.38,1439.22) 5712.38,1439.22 5712.38,1363.85 ccw(c5725.38,1363.85) 5738.38,1363.85 5738.38,1439.2 cw(c5751.38,1439.2) 5764.38,1439.2 5764.38,1363.84 ccw(c5777.38,1363.84) 5790.38,1363.84 5790.38,1439.19 cw(c5803.38,1439.19) 5816.38,1439.19 5816.38,1363.82 ccw(c5829.38,1363.82) 5842.38,1363.82 5842.38,1439.17 cw(c5855.38,1439.17) 5868.38,1439.17 5868.38,1363.81 ccw(c5881.38,1363.81) 5894.38,1363.81 5894.38,1439.16 cw(c5907.38,1439.16) 5920.38,1439.16 5920.38,1363.79 ccw(c5933.38,1363.79) 5946.38,1363.79 5946.38,1439.15 cw(c5959.38,1439.15) 5972.38,1439.15 5972.38,1363.78 ccw(c5985.38,1363.78) 5998.38,1363.78 5998.38,1439.13 cw(c6011.38,1439.13) 6024.38,1439.13 6024.38,1363.77 ccw(c6037.38,1363.77) 6050.38,1363.77 6050.38,1439.12 cw(c6063.38,1439.12) 6076.38,1439.12 6076.38,1363.75 ccw(c6089.38,1363.75) 6102.38,1363.75 6102.38,1439.1 cw(c6115.38,1439.1) 6128.38,1439.1 6128.38,1363.74 ccw(c6141.38,1363.74) 6154.38,1363.74 6154.38,1439.09 cw(c6167.38,1439.09) 6180.38,1439.09 6180.38,1363.72 ccw(c6193.38,1363.72) 6206.38,1363.72 6206.38,1439.07 cw(c6219.38,1439.07) 6232.38,1439.07 6232.38,1363.71 ccw(c6245.38,1363.71) 6258.38,1363.71 6258.38,1439.06 cw(c6271.38,1439.06) 6284.38,1439.06 6284.38,1363.69 ccw(c6297.38,1363.69) 6310.38,1363.69 6310.38,1439.04 cw(c6323.38,1439.04) 6336.38,1439.04 6336.38,1363.68 ccw(c6349.38,1363.68) 6362.38,1363.68 6362.38,1439.03 cw(c6375.38,1439.03) 6388.38,1439.03 6388.38,1363.66 ccw(c6401.38,1363.66) 6414.38,1363.66 6414.38,1437 cw(c6427.38,1437) 6427.38,1450 6445.04,1450 J5.48@7660,1450
DOUT1_B1: J2.19 J5.39 | length 6944.7
  Mid-Layer 2 w6: J2.19@1704.18,2050 1649.18,2105 1555,2105 1485,2035 1485,1880 1590,1775 2900,1775 3575,1100 5325,1100 5375,1150 J5.39@7660,1150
